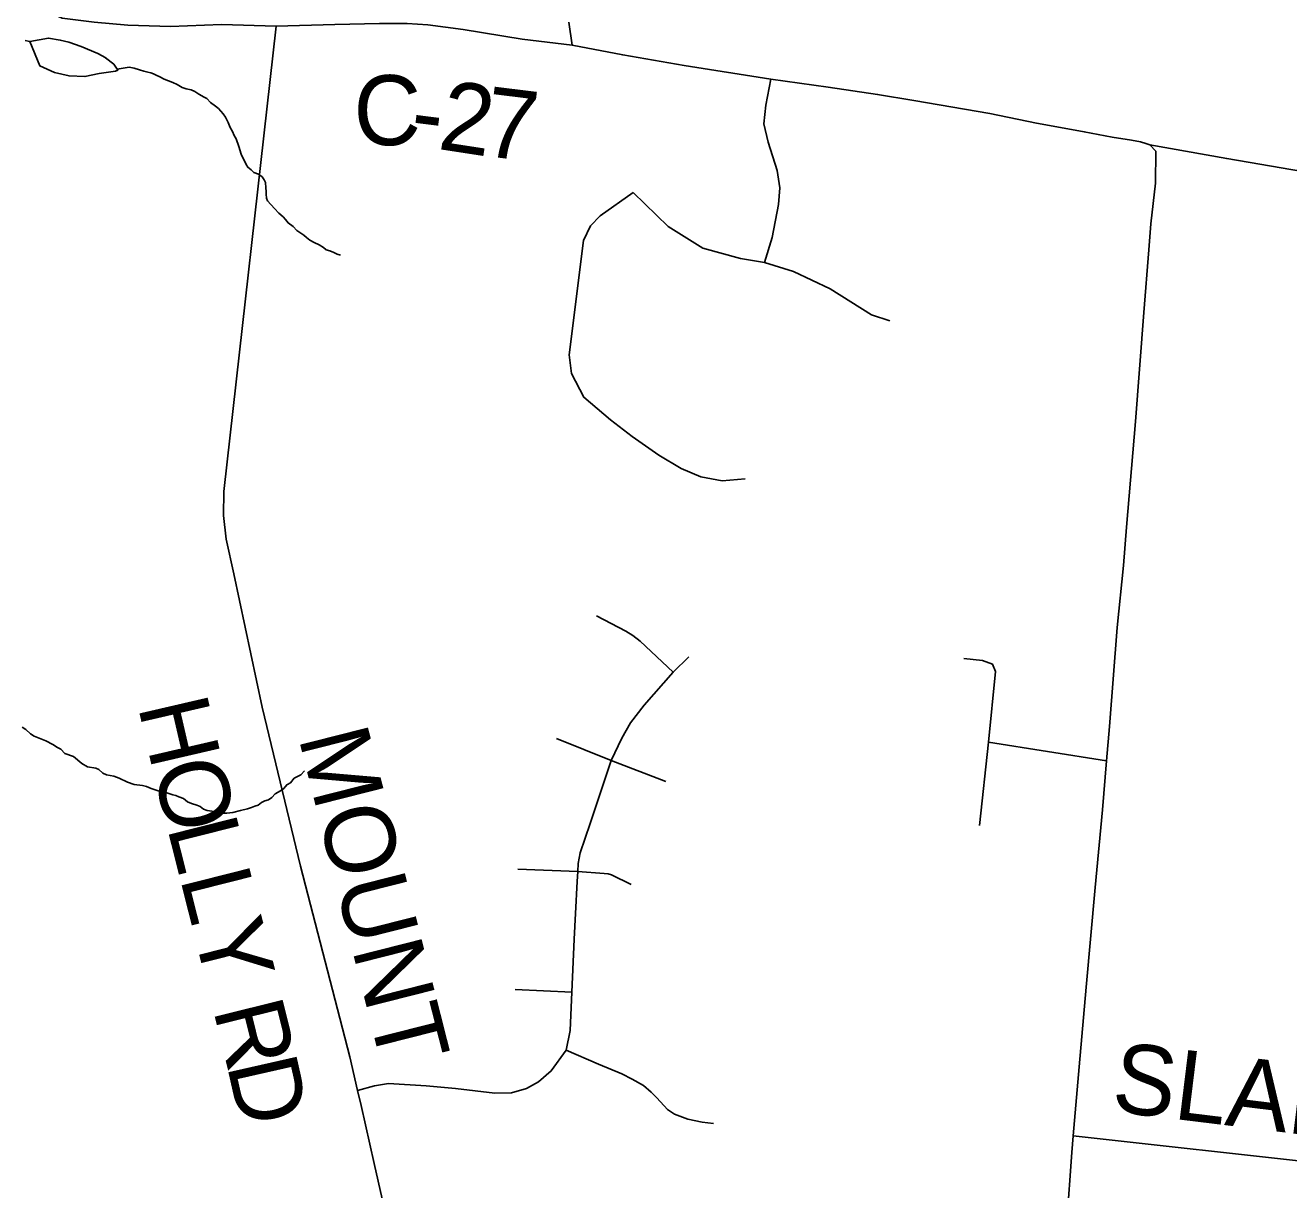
# Model space of a CAD drawing. Extents: x 0 to 39.3, y -3.9 to 22.
# Drawn here: x 6.099 to 7.125, y 17.777 to 18.722 of the extents above; entities that cross this region are included whole.
import ezdxf

# ---------------------------------------------------------------- set-up
doc = ezdxf.new("R2010")
doc.units = 0
for name, color, linetype in [('GM_X_County_Road', 7, 'Continuous'), ('GM_X_County_Road_Text', 7, 'Continuous'), ('GM_X_Minor_Lake', 7, 'Continuous'), ('GM_X_Minor_River', 7, 'Continuous'), ('GM_X_State_Route', 7, 'Continuous'), ('GM_X_Township_Road', 7, 'Continuous'), ('GM_X_Township_Road_Text', 7, 'Continuous')]:
    doc.layers.add(name, color=color, linetype=linetype)

msp = doc.modelspace()

# ---------------------------------------------------------------- linework, layer by layer
at = {"layer": 'GM_X_County_Road'}
for points in [[(6.092, 18.7483), (6.1145, 18.7346), (6.129, 18.7282), (6.1552, 18.725), (6.1823, 18.7223), (6.217, 18.7213), (6.2584, 18.723), (6.3029, 18.7216), (6.3506, 18.723), (6.3868, 18.7237), (6.4092, 18.7237), (6.4261, 18.7227), (6.4548, 18.7188), (6.5025, 18.7111), (6.5433, 18.7061)], [(6.3783, 17.3183), (6.3863, 17.3402), (6.395, 17.4132), (6.4018, 17.4743), (6.4076, 17.5311), (6.4119, 17.5741), (6.4149, 17.6194), (6.4133, 17.6408), (6.41, 17.6636), (6.4057, 17.6877), (6.4, 17.7123), (6.3969, 17.7352), (6.3824, 17.7985), (6.3718, 17.8456), (6.369, 17.8578), (6.3627, 17.8852), (6.3225, 18.0398), (6.2916, 18.1689), (6.2686, 18.277), (6.2623, 18.3053), (6.2601, 18.3244), (6.2604, 18.3439), (6.3029, 18.7216)]]:
    msp.add_lwpolyline(points, dxfattribs=at)
at = {"layer": 'GM_X_Minor_Lake'}
for points in [[(6.1645, 18.6958), (6.1582, 18.6995), (6.1446, 18.7051), (6.1344, 18.7087), (6.1276, 18.7103), (6.1181, 18.712), (6.1029, 18.7091)], [(6.1029, 18.7091), (6.1109, 18.6893), (6.123, 18.6841), (6.1347, 18.6813), (6.1476, 18.6807), (6.1591, 18.6831), (6.1686, 18.6845), (6.1724, 18.6852), (6.1743, 18.6859), (6.171, 18.6909), (6.1643, 18.696)]]:
    msp.add_lwpolyline(points, dxfattribs=at)
at = {"layer": 'GM_X_Minor_River'}
for points in [[(6.0992, 18.7099), (6.1014, 18.7095), (6.1029, 18.7091)], [(6.1737, 18.6868), (6.1836, 18.6883), (6.1877, 18.6874), (6.1919, 18.6862), (6.1953, 18.685), (6.1987, 18.6842), (6.201, 18.6838), (6.2032, 18.683), (6.2055, 18.6818), (6.2085, 18.6806), (6.2119, 18.6787), (6.2191, 18.6759), (6.2225, 18.6743), (6.2266, 18.6719), (6.2297, 18.6707), (6.2338, 18.6699), (6.2368, 18.6687), (6.2402, 18.6664), (6.2444, 18.664), (6.2466, 18.6628), (6.2496, 18.6597), (6.2537, 18.6566), (6.256, 18.6547), (6.2597, 18.6504), (6.2616, 18.6477), (6.2638, 18.6435), (6.2656, 18.6393), (6.2675, 18.6362), (6.2689, 18.6328)], [(6.2689, 18.6328), (6.2704, 18.6301), (6.2726, 18.624), (6.2744, 18.6178), (6.2755, 18.6152), (6.277, 18.6129), (6.2784, 18.6094), (6.2799, 18.6071), (6.2825, 18.6051), (6.2848, 18.6028), (6.2886, 18.6016), (6.2916, 18.5993), (6.293, 18.597), (6.2941, 18.5947), (6.2945, 18.5905), (6.2948, 18.5874), (6.2947, 18.5852), (6.2951, 18.5821), (6.2958, 18.5798), (6.3014, 18.5736), (6.3051, 18.5698), (6.3085, 18.567), (6.3104, 18.5647), (6.3126, 18.562), (6.3167, 18.5589), (6.3197, 18.5558), (6.3254, 18.5519), (6.3276, 18.55), (6.3302, 18.548), (6.3336, 18.5461), (6.3378, 18.5441), (6.3412, 18.5421), (6.3434, 18.5402), (6.3464, 18.5394), (6.3498, 18.5378), (6.3525, 18.5366), (6.3551, 18.5358)], [(6.0966, 18.1527), (6.0996, 18.1508), (6.1034, 18.1473), (6.1064, 18.1453), (6.1158, 18.1417), (6.1215, 18.1386), (6.1252, 18.1362), (6.1279, 18.1347), (6.1312, 18.1312), (6.1384, 18.1288), (6.1452, 18.1233), (6.1497, 18.1206), (6.1565, 18.1193), (6.1588, 18.1182), (6.1621, 18.1154), (6.1652, 18.1139), (6.1712, 18.113), (6.1754, 18.1114), (6.1822, 18.1079), (6.1875, 18.1062), (6.1943, 18.1054), (6.1977, 18.1045), (6.2015, 18.103), (6.2071, 18.101), (6.2132, 18.0997), (6.2189, 18.0977), (6.2215, 18.0973), (6.2238, 18.0961), (6.2276, 18.0949), (6.2309, 18.0922), (6.234, 18.0906), (6.2385, 18.0894), (6.2411, 18.0882), (6.2438, 18.0862), (6.2468, 18.085), (6.2525, 18.0842), (6.2555, 18.0837), (6.2597, 18.0829), (6.2627, 18.0829), (6.2677, 18.0835), (6.2738, 18.0849), (6.2795, 18.0864), (6.2829, 18.0875), (6.2856, 18.0885), (6.2883, 18.0893), (6.291, 18.0915), (6.2937, 18.093), (6.2967, 18.0937), (6.2994, 18.0955), (6.3021, 18.0985), (6.3064, 18.1011), (6.3091, 18.103), (6.3114, 18.106), (6.3145, 18.1074), (6.3176, 18.1112), (6.3229, 18.1141), (6.326, 18.1171)]]:
    msp.add_lwpolyline(points, dxfattribs=at)
at = {"layer": 'GM_X_State_Route'}
for points in [[(6.5433, 18.7061), (6.5405, 18.7249)], [(7.0123, 18.6254), (7.0089, 18.6265), (7.0045, 18.6278), (6.9973, 18.6292), (6.9817, 18.6316), (6.959, 18.6359), (6.9397, 18.6394), (6.9203, 18.643), (6.8823, 18.6507), (6.8205, 18.6613), (6.7912, 18.6662), (6.751, 18.672), (6.7045, 18.6785), (6.6342, 18.6898), (6.5842, 18.6983), (6.5433, 18.7061)], [(6.9771, 18.1253), (6.9794, 18.1532), (6.9857, 18.2335), (6.9907, 18.284), (6.9934, 18.3149), (7.0007, 18.4008), (7.0073, 18.4893), (7.0113, 18.54), (7.0131, 18.5612), (7.0169, 18.5942), (7.017, 18.6203), (7.0123, 18.6254)], [(6.9449, 17.7512), (6.9489, 17.8075), (6.9501, 17.8209), (6.9549, 17.8771), (6.9604, 17.9417), (6.9677, 18.0226), (6.9738, 18.0857), (6.9771, 18.1253)]]:
    msp.add_lwpolyline(points, dxfattribs=at)
at = {"layer": 'GM_X_Township_Road'}
for p, q in [((6.8738, 18.0728), (6.8811, 18.1406)), ((6.497, 17.9398), (6.543, 17.9377))]:
    msp.add_line(p, q, dxfattribs=at)
for points in [[(6.6994, 18.5297), (6.7056, 18.5502), (6.7108, 18.5769), (6.7118, 18.5904), (6.7096, 18.6046), (6.7024, 18.6275), (6.6989, 18.6423), (6.7005, 18.6576), (6.7045, 18.6785)], [(7.0123, 18.6254), (7.0747, 18.6141), (7.1456, 18.6021), (7.1894, 18.5933), (7.2273, 18.5843), (7.2361, 18.5811)], [(6.6837, 18.3543), (6.665, 18.3525), (6.6477, 18.3559), (6.6316, 18.3625), (6.6135, 18.3733), (6.5919, 18.3886), (6.5744, 18.4022), (6.5528, 18.4204), (6.5426, 18.4398), (6.5408, 18.4548), (6.5525, 18.5476), (6.558, 18.5597), (6.566, 18.5677), (6.5927, 18.5867)], [(6.5927, 18.5867), (6.6212, 18.5589), (6.6493, 18.5414), (6.68, 18.533), (6.6994, 18.5297), (6.723, 18.5224), (6.7528, 18.5083), (6.7862, 18.4873), (6.8012, 18.4824)], [(6.563, 18.2429), (6.5869, 18.2307), (6.5925, 18.227), (6.5984, 18.2226), (6.6252, 18.1973)], [(6.369, 17.8578), (6.3828, 17.8617), (6.3941, 17.8634), (6.4246, 17.8617), (6.4486, 17.8594), (6.4804, 17.8557), (6.4939, 17.8559), (6.5062, 17.8594), (6.5159, 17.8649), (6.5262, 17.8737), (6.5384, 17.8904), (6.5417, 17.9065), (6.543, 17.9377), (6.5447, 17.9806), (6.5459, 18.0015), (6.5472, 18.0273), (6.5478, 18.0355), (6.5482, 18.042), (6.5498, 18.0508), (6.5579, 18.0746), (6.5749, 18.1255), (6.5834, 18.1438), (6.5906, 18.1562), (6.6017, 18.1705), (6.6252, 18.1973), (6.6379, 18.2097)], [(6.8611, 18.2085), (6.8763, 18.2068), (6.8845, 18.2037), (6.8868, 18.1978), (6.8811, 18.1406), (6.9771, 18.1253)], [(6.5305, 18.1434), (6.5749, 18.1255), (6.6192, 18.1086)], [(6.4991, 18.0375), (6.5478, 18.0355), (6.5691, 18.034), (6.5724, 18.0335), (6.5751, 18.0328), (6.591, 18.0249)], [(6.5384, 17.8904), (6.5647, 17.8792), (6.5835, 17.8712), (6.592, 17.8669), (6.601, 17.8619), (6.6074, 17.8563), (6.612, 17.8517), (6.6207, 17.8424), (6.6262, 17.8387), (6.637, 17.8344), (6.6488, 17.8321), (6.658, 17.8311)], [(6.9501, 17.8209), (7.1548, 17.7982), (7.1802, 17.7959), (7.3014, 17.7825), (7.3342, 17.7757), (7.341, 17.7736), (7.35, 17.7696), (7.3605, 17.7651), (7.3687, 17.7619), (7.3792, 17.7582), (7.3924, 17.7544), (7.4026, 17.7515), (7.4127, 17.7482)]]:
    msp.add_lwpolyline(points, dxfattribs=at)

# ---------------------------------------------------------------- texts
at = {"layer": 'GM_X_County_Road_Text'}
for s, height, rotation, p in [('C', 0.0568, 359.6839, (6.3655, 18.6252)), ('2', 0.0568, 351.2598, (6.4331, 18.6221)), ('7', 0.0568, 352.9891, (6.4695, 18.6166)), ('-', 0.0568, 352.7685, (6.4103, 18.625)), ('H', 0.0568, 283.0476, (6.1905, 18.1699)), ('MOUNT', 0.05682, 284.2166, (6.3208, 18.1445)), ('O', 0.0568, 284.0398, (6.2021, 18.1202)), ('L', 0.0568, 284.1711, (6.2142, 18.0715)), ('L', 0.0568, 284.1831, (6.2246, 18.0303)), ('Y', 0.0568, 284.1758, (6.235, 17.9891)), ('R', 0.0568, 283.97, (6.2515, 17.9237)), ('D', 0.0568, 282.7418, (6.2627, 17.8787))]:
    msp.add_text(s, height=height, rotation=rotation, dxfattribs=at).set_placement(p)
at = {"layer": 'GM_X_Township_Road_Text'}
msp.add_text('SLADE', height=0.05682, rotation=353.0055, dxfattribs=at).set_placement((6.98, 17.8411))

doc.saveas('drawing.dxf')
